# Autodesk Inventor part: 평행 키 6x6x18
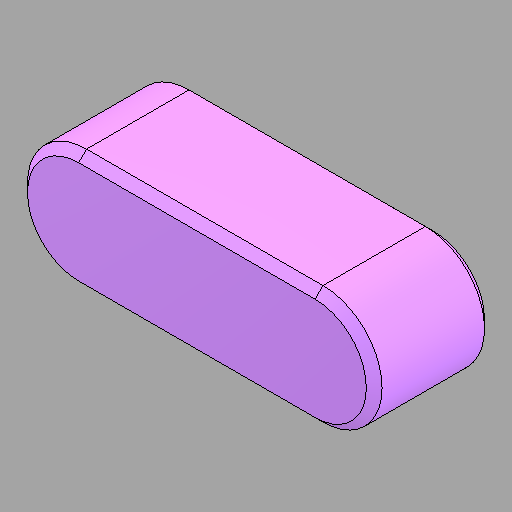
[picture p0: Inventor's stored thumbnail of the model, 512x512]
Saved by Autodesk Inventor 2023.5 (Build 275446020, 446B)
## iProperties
Created: 2025-07
Part Number: 평행 키 6x6x18
Material: 강철, 연강
Description: 키 및 해당 키홈
Document SubType Name: Modeling
Designer: 1강의실14
Density: 7.85 g/cm^3
Appearance: 기본값
Author: jhkim
Sending System: Autodesk Inventor 2026
Preprocessor: ST-DEVELOPER v20.1
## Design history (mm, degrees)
feature "Solid1"
node "솔리드1"
